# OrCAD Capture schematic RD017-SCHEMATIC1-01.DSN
size A3
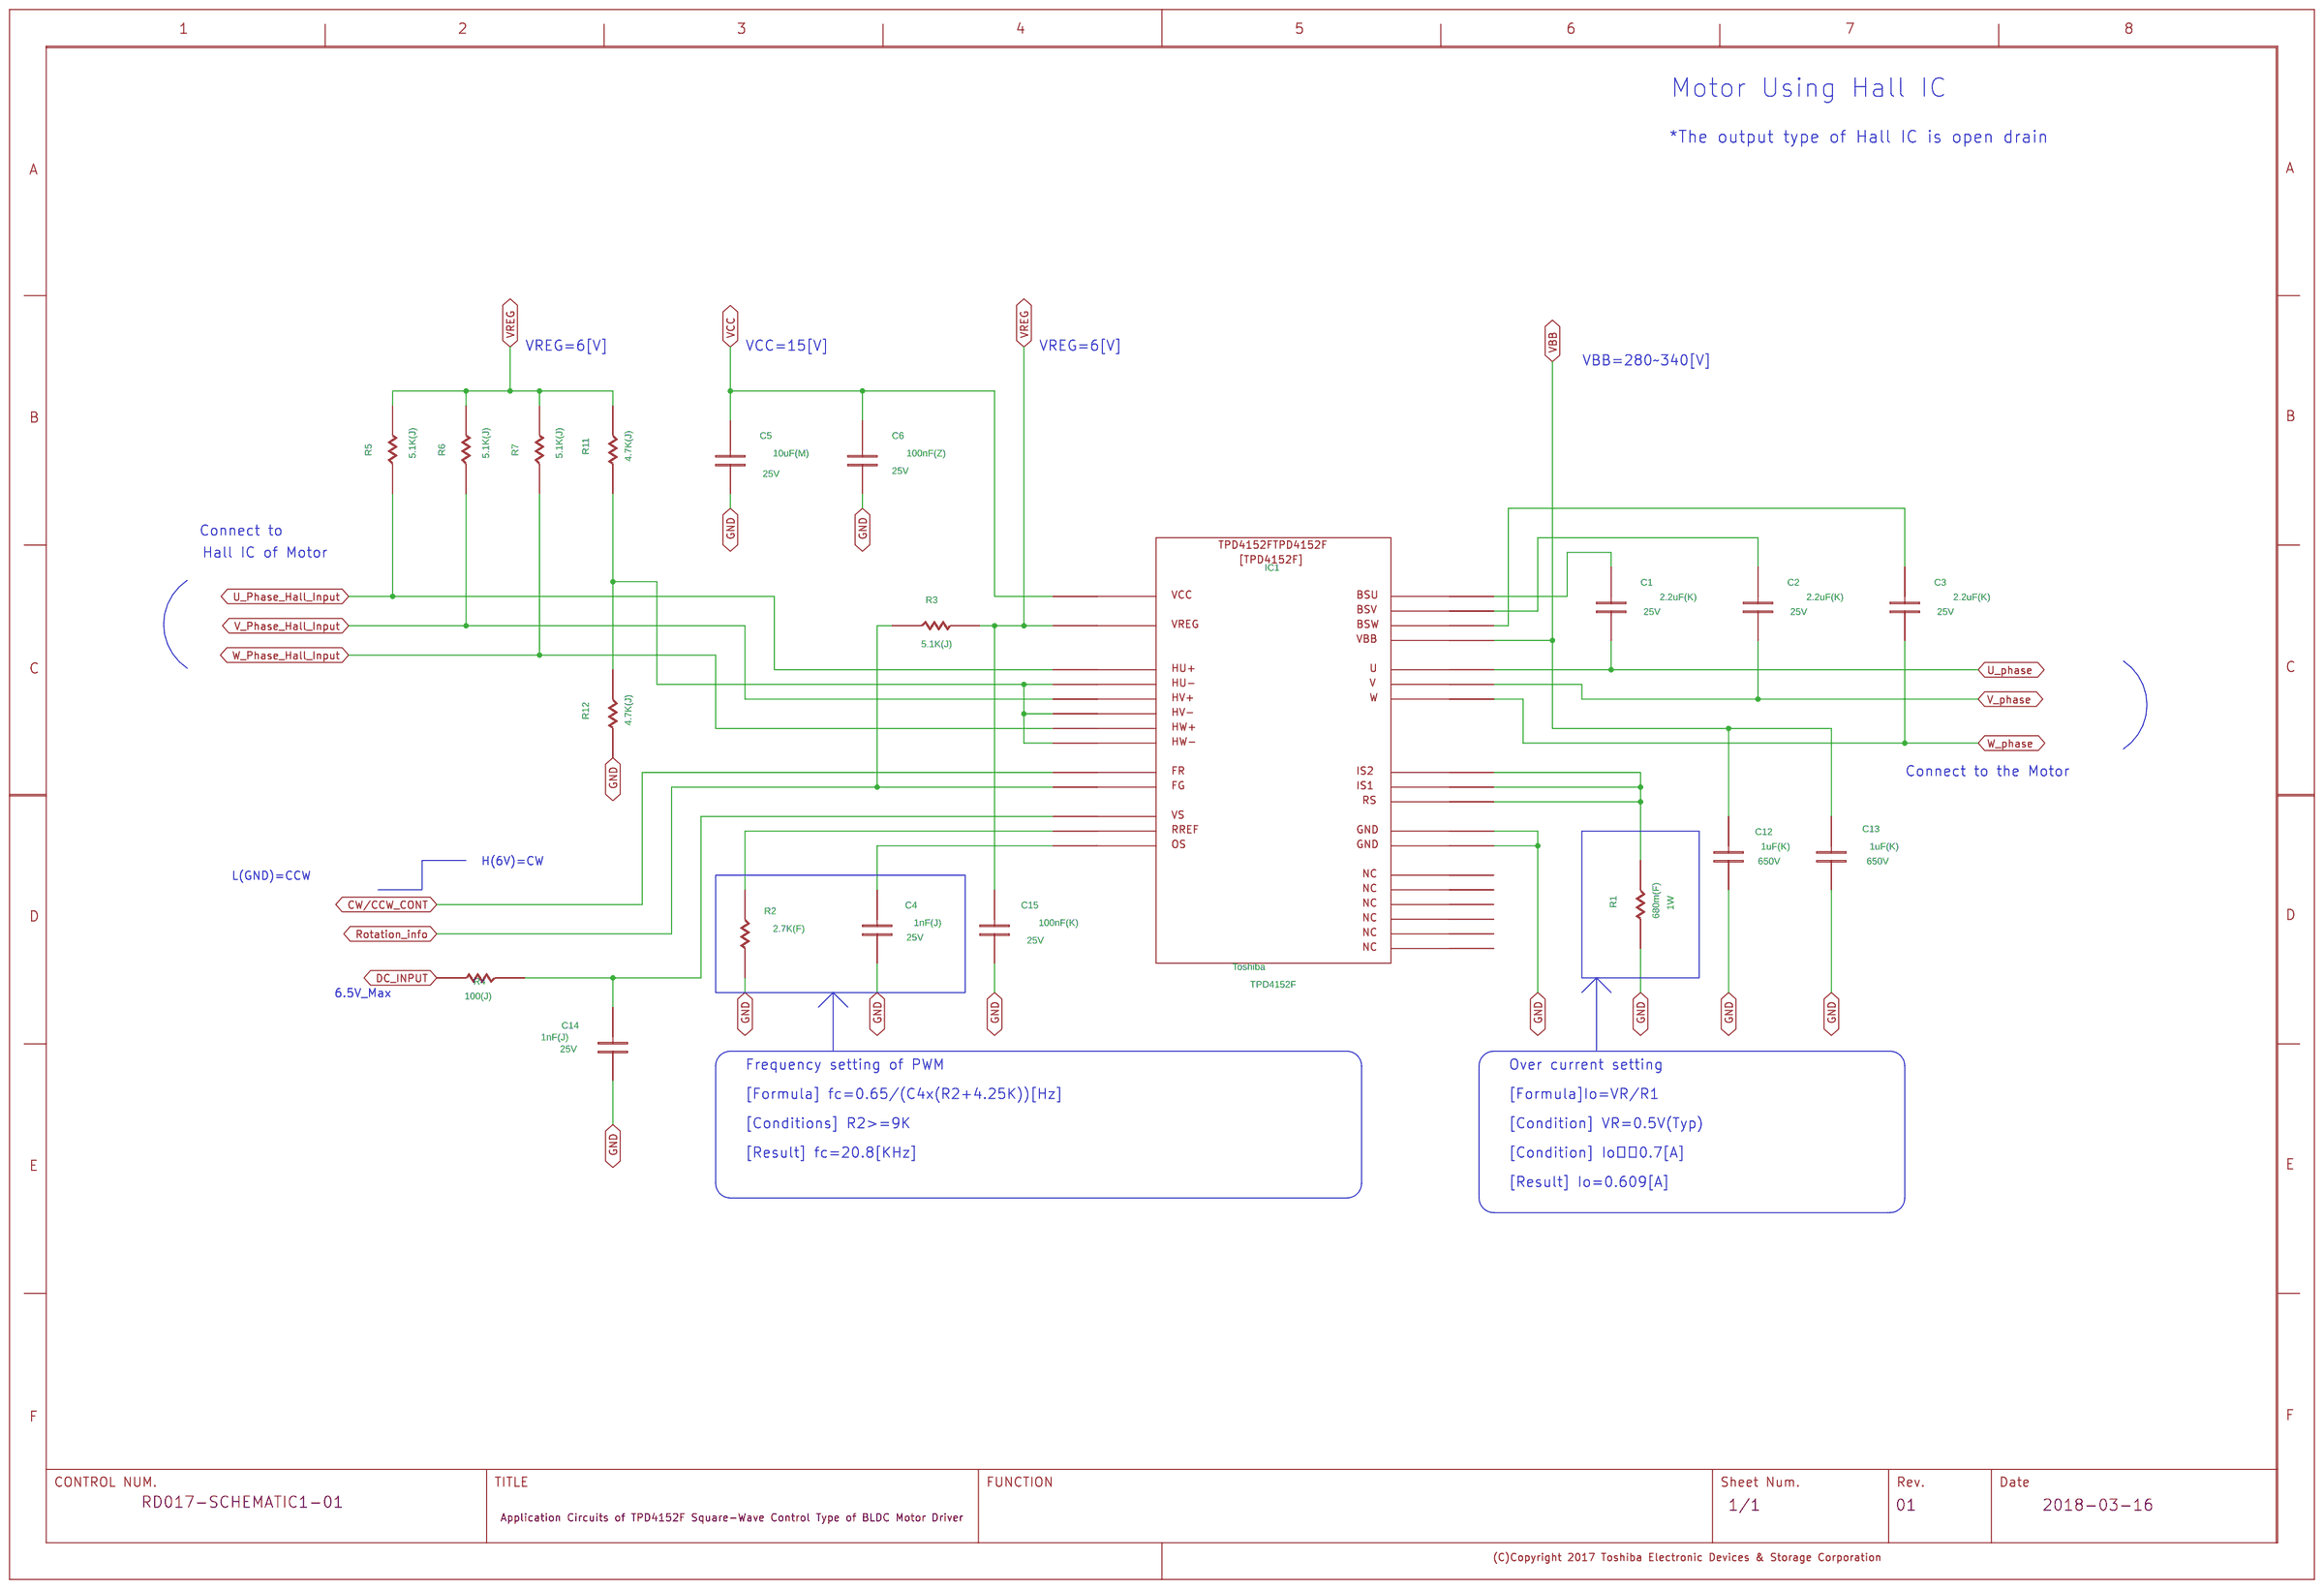
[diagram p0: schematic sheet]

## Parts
C1  C
C2  C
C3  C
C4  C
C5  C
C6  C
C12  C
C13  C
C14  C
C15  C
IC1  S-TPD4152F
R1  R
R2  R
R3  R
R4  R
R5  R
R6  R
R7  R
R11  R
R12  R
U?#1  WAKU_DEF100

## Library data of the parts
C1-C3 = C: COMPONENTTYPE: 4; GCOUNT: 1; MAXGCOUNT: 1; SIZECODESMD: 2012; VAL1: 2.2uF(K); VAL2: 25V
C4 C14 = C: COMPONENTTYPE: 4; GCOUNT: 1; MAXGCOUNT: 1; SIZECODESMD: 1608; VAL1: 1nF(J); VAL2: 25V
C5 = C: COMPONENTTYPE: 4; GCOUNT: 1; MAXGCOUNT: 1; SIZECODESMD: 1608; VAL1: 10uF(M); VAL2: 25V
C6 = C: COMPONENTTYPE: 4; GCOUNT: 1; MAXGCOUNT: 1; SIZECODESMD: 1608; VAL1: 100nF(Z); VAL2: 25V
C12 C13 = C: COMPONENTTYPE: 4; GCOUNT: 1; MAXGCOUNT: 1; SIZECODESMD: DIP; VAL1: 1uF(K); VAL2: 650V; VAL3: ECQE6105KF
C15 = C: COMPONENTTYPE: 4; GCOUNT: 1; MAXGCOUNT: 1; SIZECODESMD: 1608; VAL1: 100nF(K); VAL2: 25V
IC1 = S-TPD4152F: COMPONENTTYPE: 4; SIZECODESMD: HSSOP31; USERCOMPTEXT1: Toshiba; VAL1: TPD4152F; VAL3: TPD4152F
R1 = R: COMPONENTTYPE: 4; GCOUNT: 1; MAXGCOUNT: 1; SIZECODESMD: 6332; VAL1: 680m(F); VAL2: 1W; VAL3: SL1TTER85F
R2 = R: COMPONENTTYPE: 4; GCOUNT: 1; MAXGCOUNT: 1; SIZECODESMD: 1608; VAL1: 2.7K(F); VAL2: 100mW
R3 R5-R7 = R: COMPONENTTYPE: 4; GCOUNT: 1; MAXGCOUNT: 1; SIZECODESMD: 1608; VAL1: 5.1K(J); VAL2: 100mW
R4 = R: COMPONENTTYPE: 4; GCOUNT: 1; MAXGCOUNT: 1; SIZECODESMD: 1608; VAL1: 100(J); VAL2: 100mW
R11 R12 = R: COMPONENTTYPE: 4; GCOUNT: 1; MAXGCOUNT: 1; SIZECODESMD: 1608; VAL1: 4.7K(J); VAL2: 100mW
U?#1 = WAKU_DEF100: COMPONENTTYPE: 2; DATE: 2018-03-16; DRAWINGNUMBER: RD017-SCHEMATIC1-01; REVISION: 01; SHEETNUMBER: 1/1; TITLE: Application Circuits of TPD4152F Square-Wave Control Type of BLDC Motor Driver; UPDATEDATE: 2018/03/16; UPDATETIME: 18:01:41; UPDATEUSER: g4302510

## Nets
GND: C4.1 C5.1 C6.1 C12.1 C13.1 C14.1 C15.1 IC1.11 IC1.31 R1.1 R2.1 R12.1
VCC: C5.2 C6.2 IC1.18
CW/CCW_CONT: IC1.22
DC_INPUT: R4.1
Rotation_info: IC1.20 R3.2
U_phase: C1.1 IC1.9
U_Phase_Hall_Input: IC1.29 R5.2
V_phase: C2.1 IC1.6
V_Phase_Hall_Input: IC1.27 R6.2
VBB: C12.2 C13.2 IC1.4
VREG: C15.2 IC1.19 R3.1 R5.1 R6.1 R7.1 R11.2
W_phase: C3.1 IC1.2
W_Phase_Hall_Input: IC1.24 R7.2
N00457: C1.2 IC1.10
N00467: C2.2 IC1.5
N00477: C3.2 IC1.3
N00487: IC1.1 IC1.7 IC1.14 R1.2
N00529: IC1.16 R2.2
N00535: C4.2 IC1.17
N00651: IC1.23 IC1.26 IC1.28 R11.1 R12.2
N00677: C14.2 IC1.15 R4.2

Not connected (* = marked no-connect by the designer): IC1 8 12 13 21 25 30

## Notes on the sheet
- Motor Using Hall IC
- *The output type of Hall IC is open drain
- VREG=6[V]
- VCC=15[V]
- VREG=6[V]
- VBB=280~340[V]
- Connect to
- Hall IC of Motor
- Connect to the Motor
- H(6V)=CW
- L(GND)=CCW
- 6.5V_Max
- Frequency setting of PWM
- Over current setting
- [Formula] fc=0.65/(C4x(R2+4.25K))[Hz]
- [Formula]Io=VR/R1
- [Conditions] R2>=9K
- [Condition] VR=0.5V(Typ)
- [Result] fc=20.8[KHz]
- [Condition] Io0.7[A]
- [Result] Io=0.609[A]
